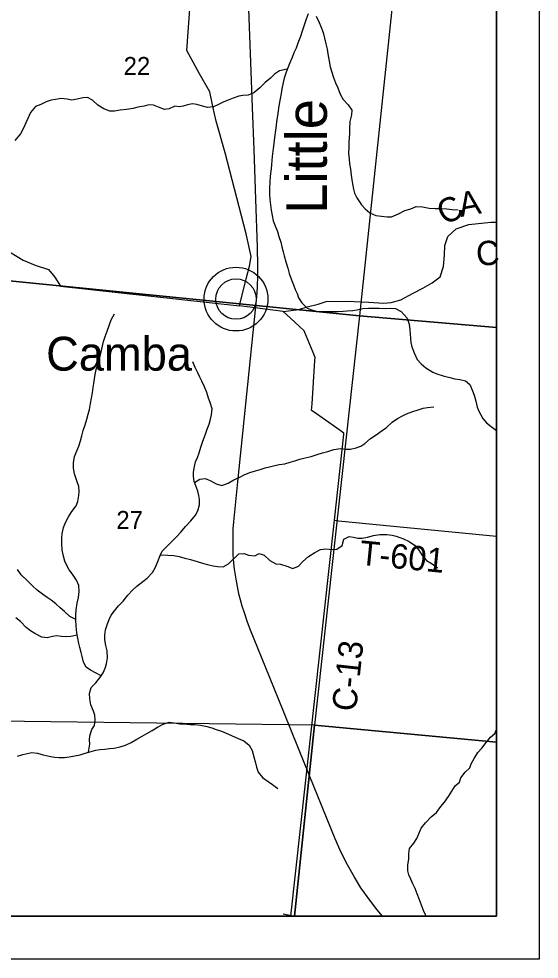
# Model space of a CAD drawing. Extents: x 0 to 34, y 0 to 22.
# Drawn here: x 29.202 to 30.417, y 14 to 16.193 of the extents above; entities that cross this region are included whole.
import ezdxf

# ---------------------------------------------------------------- set-up
doc = ezdxf.new("R2010")
doc.units = 0
for name, color, linetype in [('GM_X_Corporation', 7, 'Continuous'), ('GM_X_County_Road', 7, 'Continuous'), ('GM_X_County_Road_Text', 7, 'Continuous'), ('GM_X_Major_River', 7, 'Continuous'), ('GM_X_Major_River_Text', 7, 'Continuous'), ('GM_X_Minor_River', 7, 'Continuous'), ('GM_X_Rail_Line', 7, 'Continuous'), ('GM_X_Section_Text', 7, 'Continuous'), ('GM_X_Township_Road', 7, 'Continuous'), ('GM_X_Township_Road_Text', 7, 'Continuous'), ('GM_X_Unincorporated', 7, 'Continuous'), ('GM_X_Unincorporated_Location', 7, 'Continuous'), ('GM_X_Unincorporated_Text', 7, 'Continuous'), ('SH_Data', 7, 'Continuous')]:
    doc.layers.add(name, color=color, linetype=linetype)

msp = doc.modelspace()

# ---------------------------------------------------------------- linework, layer by layer
at = {"layer": 'GM_X_Corporation'}
msp.add_lwpolyline([(25.8273, 14.1), (30.3167, 14.1), (30.3167, 19.5906)], dxfattribs=at)
for points in [[(30.115, 16.6136), (29.9973, 15.5007), (29.0551, 15.5941), (29.176, 16.6858)], [(30.3167, 15.4729), (30.3167, 16.5908), (30.115, 16.6136), (29.9973, 15.5007)], [(29.9973, 15.5007), (29.8921, 14.5457), (28.9075, 14.5584), (29.0551, 15.5941)], [(30.3167, 14.5061), (30.3167, 15.4729), (29.9973, 15.5007), (29.8921, 14.5457)], [(28.8409, 14.1), (29.8452, 14.1), (29.8921, 14.5457), (28.9075, 14.5584)], [(29.8452, 14.1), (30.3167, 14.1), (30.3167, 14.5061), (29.8921, 14.5457)]]:
    msp.add_lwpolyline(points, close=True, dxfattribs=at)
at = {"layer": 'GM_X_County_Road'}
msp.add_line((29.8192, 15.5102), (29.7173, 15.5239), dxfattribs=at)
for points in [[(29.7173, 15.5239), (29.7329, 15.5869), (29.7403, 15.6165), (29.7444, 15.6389), (29.7328, 15.6915), (29.684, 15.8801), (29.6625, 15.9547), (29.6552, 15.9884), (29.6478, 16.0229), (29.6238, 16.0649), (29.5944, 16.119), (29.6075, 16.3028)], [(29.8192, 15.5102), (29.8554, 15.515), (29.8754, 15.5216), (29.9004, 15.5278), (29.9193, 15.5335), (29.9673, 15.5342), (30.0191, 15.5321), (30.0539, 15.53), (30.0713, 15.5316), (30.0936, 15.5378), (30.1227, 15.5535), (30.145, 15.5646), (30.1669, 15.5772), (30.1853, 15.5913), (30.1936, 15.6152), (30.1957, 15.6422), (30.196, 15.6646), (30.2035, 15.6854), (30.2231, 15.7034), (30.2522, 15.7137), (30.3036, 15.7189), (30.3167, 15.7188)], [(29.1663, 15.6581), (29.2121, 15.6303), (29.2398, 15.6186), (29.2716, 15.6086), (29.2861, 15.5904), (29.2994, 15.5696), (29.7173, 15.5239)], [(29.8366, 14.1), (29.9385, 15.0235), (29.9605, 15.2238), (29.9608, 15.2264), (29.9465, 15.2365), (29.8887, 15.2769), (29.8854, 15.2792), (29.8864, 15.2953), (29.8932, 15.3958), (29.8937, 15.4033), (29.8889, 15.415), (29.8699, 15.4616), (29.8683, 15.4656), (29.8566, 15.4763), (29.8267, 15.5034), (29.8192, 15.5102)]]:
    msp.add_lwpolyline(points, dxfattribs=at)
at = {"layer": 'GM_X_Major_River'}
for points in [[(29.8773, 16.2045), (29.8726, 16.1924), (29.868, 16.1784), (29.8637, 16.164), (29.8598, 16.1515), (29.8536, 16.136), (29.849, 16.1247), (29.8436, 16.1138), (29.8397, 16.1028), (29.8343, 16.0907), (29.8297, 16.0786), (29.8262, 16.0688), (29.8215, 16.0544), (29.8192, 16.0442), (29.816, 16.0295), (29.8144, 16.0189), (29.812, 16.0064), (29.8092, 15.9901), (29.8072, 15.9787), (29.8056, 15.967), (29.8036, 15.9538), (29.8024, 15.9439), (29.8012, 15.9333), (29.7991, 15.9166), (29.7971, 15.9026), (29.7955, 15.8905), (29.7935, 15.8716), (29.7918, 15.8534), (29.7909, 15.8435), (29.7889, 15.8261), (29.7876, 15.8117), (29.7871, 15.7977), (29.787, 15.7837), (29.788, 15.7715), (29.7894, 15.7594), (29.7908, 15.7465), (29.793, 15.734), (29.7959, 15.7222), (29.8, 15.71), (29.8055, 15.6974), (29.8092, 15.6857), (29.8132, 15.672), (29.8162, 15.6613), (29.8191, 15.6496), (29.8217, 15.6401), (29.8253, 15.6264), (29.8297, 15.6115), (29.833, 15.599), (29.8386, 15.5845), (29.8434, 15.5724), (29.8474, 15.5617), (29.8515, 15.5522), (29.8552, 15.5427), (29.8626, 15.5305), (29.875, 15.5183), (29.8848, 15.514), (29.8991, 15.5108), (29.9124, 15.5107), (29.9222, 15.5102)], [(29.9222, 15.5102), (29.9335, 15.5101), (29.9475, 15.5108), (29.9588, 15.5114), (29.9687, 15.5117), (29.9815, 15.5131), (29.9914, 15.5142), (30.0046, 15.5171), (30.0179, 15.5181), (30.0432, 15.5179), (30.0575, 15.5174), (30.0689, 15.518), (30.081, 15.5172), (30.0941, 15.5106), (30.1084, 15.4949), (30.1128, 15.4812), (30.1145, 15.468), (30.1156, 15.4581), (30.1163, 15.4478), (30.1173, 15.438), (30.1191, 15.4281), (30.1246, 15.4137), (30.1317, 15.3988), (30.1411, 15.3881), (30.1519, 15.3793), (30.1681, 15.3693), (30.1779, 15.3654), (30.1926, 15.3603), (30.208, 15.3564), (30.2201, 15.3537), (30.2311, 15.3517), (30.2443, 15.3485), (30.2551, 15.3401), (30.2611, 15.3256), (30.2651, 15.315), (30.2684, 15.3013), (30.2721, 15.2876), (30.2761, 15.2777), (30.2847, 15.261), (30.294, 15.2506), (30.3049, 15.2426), (30.3167, 15.2328)]]:
    msp.add_lwpolyline(points, dxfattribs=at)
at = {"layer": 'GM_X_Minor_River'}
for points in [[(29.8964, 16.1991), (29.9027, 16.1846), (29.9072, 16.1748), (29.9121, 16.1611), (29.9188, 16.1345), (29.9217, 16.122), (29.9236, 16.1114), (29.9265, 16.0939), (29.9291, 16.0814), (29.9317, 16.0712), (29.9369, 16.056), (29.9414, 16.0435), (29.9467, 16.0324), (29.9519, 16.0172), (29.9594, 16.0047), (29.9711, 15.9925), (29.9793, 15.9796), (29.9789, 15.9694), (29.9747, 15.9535), (29.9742, 15.9353), (29.9742, 15.9258), (29.9726, 15.9061), (29.9725, 15.894), (29.9717, 15.8788), (29.9728, 15.8659), (29.9742, 15.8549), (29.9761, 15.8424), (29.9779, 15.8283), (29.979, 15.8177), (29.9808, 15.8079), (29.9831, 15.7961), (29.9857, 15.7866), (29.9909, 15.7752), (30.0018, 15.7592), (30.0101, 15.7497), (30.0214, 15.7402), (30.035, 15.7345), (30.0486, 15.7329), (30.0614, 15.7313), (30.072, 15.7309), (30.0886, 15.738), (30.103, 15.7459), (30.1167, 15.75), (30.1295, 15.7553), (30.1439, 15.7548), (30.1601, 15.7517), (30.1741, 15.7505), (30.1892, 15.7508), (30.2009, 15.7496), (30.2138, 15.7484), (30.2278, 15.7472)], [(29.8286, 16.0755), (29.8104, 16.0717), (29.7986, 16.0638), (29.7892, 16.0548), (29.7774, 16.0446), (29.7649, 16.0317), (29.7508, 16.0204), (29.7372, 16.0152), (29.7251, 16.0141), (29.7153, 16.0123), (29.702, 16.0078), (29.6907, 16.0029), (29.6808, 15.9991), (29.6664, 15.9924), (29.6566, 15.9879), (29.6426, 15.9864), (29.6309, 15.9891), (29.6173, 15.993), (29.6075, 15.9946), (29.5958, 15.9927), (29.5859, 15.9893), (29.5761, 15.9879), (29.5659, 15.9891), (29.553, 15.9827), (29.5417, 15.9816), (29.5277, 15.9873), (29.5164, 15.9919), (29.5054, 15.9924), (29.4948, 15.9894), (29.4801, 15.9868), (29.4691, 15.9838), (29.4532, 15.9816), (29.4385, 15.9802), (29.4256, 15.9779), (29.4143, 15.9776), (29.4007, 15.983), (29.3867, 15.9918), (29.3743, 16.0036), (29.3623, 16.0097), (29.3517, 16.009), (29.3384, 16.0056), (29.3248, 16.0034), (29.3146, 16.0057), (29.301, 16.0069), (29.2874, 16.0051), (29.2772, 16.0033), (29.2658, 15.9991), (29.253, 15.9935), (29.2412, 15.9883), (29.2294, 15.9743), (29.2233, 15.9607), (29.2184, 15.9504), (29.2127, 15.9383), (29.2058, 15.9247), (29.1929, 15.9092)], [(29.3942, 14.6609), (29.3825, 14.6673), (29.3693, 14.6738), (29.3595, 14.6807), (29.3528, 14.6929), (29.3498, 14.7061), (29.3476, 14.7156), (29.3442, 14.7266), (29.3424, 14.7361), (29.3394, 14.749), (29.3372, 14.7608), (29.3358, 14.7767), (29.3347, 14.7923), (29.3351, 14.8029), (29.3359, 14.8146), (29.3383, 14.8305), (29.3413, 14.8434), (29.3429, 14.8574), (29.3422, 14.8711), (29.337, 14.884), (29.3276, 14.8977), (29.3193, 14.9083), (29.3137, 14.9178), (29.3096, 14.9284), (29.3055, 14.9429), (29.3033, 14.955), (29.3022, 14.9694), (29.3026, 14.9823), (29.3034, 14.9922), (29.3061, 15.0065), (29.3111, 15.0183), (29.3183, 15.0315), (29.326, 15.044), (29.3358, 15.0572), (29.3397, 15.067), (29.3424, 15.0811), (29.3428, 15.0905), (29.3417, 15.1023), (29.3372, 15.1159), (29.3316, 15.1315), (29.3294, 15.1452), (29.3298, 15.1573), (29.3318, 15.1721), (29.3417, 15.1967), (29.3456, 15.2092), (29.349, 15.2205), (29.3525, 15.233), (29.3567, 15.2463), (29.3605, 15.2595), (29.364, 15.2712), (29.3667, 15.2822), (29.3694, 15.2959), (29.3713, 15.308), (29.374, 15.3205), (29.3756, 15.3334), (29.3768, 15.3428), (29.3787, 15.3538), (29.3799, 15.3637), (29.3822, 15.3754), (29.3864, 15.389), (29.3899, 15.3989), (29.3937, 15.4125), (29.3968, 15.4265), (29.3999, 15.4401), (29.4033, 15.4519), (29.4083, 15.4647), (29.4129, 15.478), (29.4178, 15.4912), (29.4251, 15.5049)], [(29.3646, 14.4827), (29.3674, 14.5014), (29.3671, 14.5113), (29.3679, 14.5211), (29.3725, 14.5355), (29.3786, 14.5453), (29.3805, 14.5582), (29.3794, 14.5688), (29.3761, 14.5787), (29.3701, 14.5931), (29.3679, 14.6075), (29.3672, 14.6197), (29.371, 14.6333), (29.3817, 14.6446), (29.3923, 14.6582), (29.3992, 14.668), (29.4034, 14.6786), (29.4064, 14.6888), (29.4091, 14.7025), (29.4081, 14.7188), (29.4051, 14.7317), (29.4025, 14.7446), (29.4026, 14.7556), (29.4041, 14.7684), (29.4091, 14.7821), (29.4129, 14.7919), (29.4175, 14.8021), (29.4255, 14.8127), (29.4346, 14.8244), (29.4452, 14.835), (29.4566, 14.8493), (29.468, 14.8614), (29.4775, 14.8697), (29.4915, 14.881), (29.5014, 14.8889), (29.5143, 14.9017), (29.5212, 14.9146), (29.5261, 14.9271), (29.5319, 14.9411), (29.5368, 14.9513), (29.549, 14.9641), (29.5607, 14.9754), (29.5706, 14.9856), (29.5801, 14.9962), (29.5911, 15.0094), (29.6037, 15.0226), (29.6147, 15.0355), (29.62, 15.0453), (29.6235, 15.0597), (29.6235, 15.0722), (29.6224, 15.0817), (29.6202, 15.0912), (29.615, 15.1041), (29.6112, 15.1143), (29.6101, 15.1257), (29.6098, 15.1352), (29.611, 15.145), (29.6145, 15.1598), (29.6187, 15.17), (29.6232, 15.1806), (29.6271, 15.1939), (29.6317, 15.2082), (29.6378, 15.2241), (29.642, 15.2362), (29.6466, 15.2476), (29.6497, 15.2597), (29.652, 15.2696), (29.6532, 15.2836), (29.6487, 15.298), (29.645, 15.3086), (29.6409, 15.3215), (29.6356, 15.3345), (29.6293, 15.3481), (29.6248, 15.3576), (29.6195, 15.3675), (29.6135, 15.3797), (29.6079, 15.393)], [(29.6123, 15.1113), (29.6245, 15.1192), (29.637, 15.1207), (29.6487, 15.1161), (29.663, 15.1084), (29.6762, 15.1046), (29.691, 15.1098), (29.7038, 15.1177), (29.7167, 15.1237), (29.7277, 15.1293), (29.741, 15.135), (29.7542, 15.1387), (29.7652, 15.1421), (29.7773, 15.1458), (29.7871, 15.1484), (29.7992, 15.1514), (29.8098, 15.154), (29.8227, 15.1554), (29.8355, 15.1588), (29.8461, 15.1622), (29.8583, 15.1663), (29.8704, 15.1693), (29.8847, 15.1722), (29.8987, 15.1767), (29.9109, 15.1808), (29.923, 15.1842), (29.937, 15.1883), (29.9525, 15.1909), (29.9661, 15.1897), (29.9759, 15.1896), (29.9891, 15.1922), (30.0001, 15.1967), (30.01, 15.2027), (30.0232, 15.2144), (30.0361, 15.2227), (30.0502, 15.2329), (30.0604, 15.2397), (30.0733, 15.2521), (30.0862, 15.2612), (30.0972, 15.2675), (30.107, 15.2717), (30.1218, 15.2773), (30.1339, 15.2814), (30.146, 15.2851), (30.1562, 15.2862), (30.1706, 15.2881)], [(29.5329, 14.9432), (29.55, 14.9421), (29.5636, 14.9417), (29.5765, 14.939), (29.5893, 14.9355), (29.6029, 14.932), (29.6184, 14.9274), (29.6308, 14.9232), (29.6425, 14.9201), (29.6557, 14.9174), (29.6659, 14.9158), (29.6788, 14.915), (29.6917, 14.9218), (29.7152, 14.9452), (29.7277, 14.9459), (29.7382, 14.9424), (29.7526, 14.9408), (29.7632, 14.9461), (29.7749, 14.9419), (29.7881, 14.9301), (29.8016, 14.9221), (29.813, 14.9212), (29.8273, 14.9162), (29.8413, 14.9113), (29.8549, 14.9165), (29.8648, 14.9275), (29.8781, 14.9391), (29.8928, 14.9486), (29.9061, 14.9553), (29.9186, 14.9568), (29.9344, 14.9552), (29.9446, 14.9563), (29.9564, 14.9649), (29.9606, 14.9797), (29.9727, 14.9857), (29.9833, 14.9842), (29.9931, 14.9818), (30.0033, 14.9818), (30.0158, 14.984), (30.0302, 14.9881), (30.045, 14.9903), (30.0608, 14.9902), (30.0733, 14.9891), (30.0831, 14.9867), (30.0997, 14.9806), (30.1129, 14.9737), (30.1253, 14.9657), (30.1359, 14.9535), (30.1438, 14.9417), (30.1539, 14.9299), (30.1667, 14.9219), (30.1795, 14.9128)], [(29.3347, 14.7923), (29.3207, 14.7991), (29.3083, 14.8109), (29.2985, 14.8197), (29.2887, 14.8288), (29.2778, 14.8376), (29.268, 14.8437), (29.2575, 14.8514), (29.2447, 14.8609), (29.2349, 14.87), (29.2217, 14.8834), (29.2078, 14.8967), (29.1991, 14.9089)], [(29.3381, 14.7557), (29.3236, 14.7525), (29.3137, 14.7518), (29.302, 14.7526), (29.2911, 14.7542), (29.2808, 14.7523), (29.268, 14.7497), (29.2555, 14.7513), (29.2397, 14.7597), (29.2295, 14.7658), (29.2193, 14.7738), (29.2058, 14.7872), (29.1952, 14.7963)], [(29.1991, 14.4737), (29.2112, 14.4775), (29.2324, 14.4819), (29.2456, 14.4803), (29.2592, 14.4769), (29.2728, 14.4738), (29.2853, 14.4714), (29.2951, 14.4703), (29.3087, 14.4706), (29.3193, 14.4721), (29.3329, 14.4739), (29.345, 14.4765), (29.3549, 14.4799), (29.3677, 14.4836), (29.3821, 14.4873), (29.392, 14.4892), (29.4025, 14.4899), (29.4135, 14.491), (29.4237, 14.492), (29.4388, 14.495), (29.4513, 14.4991), (29.4646, 14.5051), (29.4771, 14.513), (29.4896, 14.5202), (29.5006, 14.5266), (29.5135, 14.5333), (29.526, 14.5412), (29.5392, 14.5484), (29.5529, 14.5525), (29.5646, 14.5513), (29.5778, 14.5486), (29.5876, 14.5485), (29.602, 14.5477), (29.6125, 14.5473), (29.6258, 14.5457), (29.6375, 14.5438), (29.6522, 14.5399), (29.6628, 14.5357), (29.6748, 14.5318), (29.6858, 14.5273), (29.6982, 14.5219), (29.7141, 14.515), (29.7269, 14.5089), (29.7393, 14.4993), (29.7468, 14.4868), (29.7502, 14.472), (29.7543, 14.4576), (29.7569, 14.4481), (29.7606, 14.4363), (29.7704, 14.4234), (29.7843, 14.4146), (29.7941, 14.4074), (29.8069, 14.3982)], [(30.1528, 14.1), (30.1511, 14.1037), (30.1462, 14.1136), (30.1421, 14.1261), (30.1372, 14.1383), (30.132, 14.1523), (30.1268, 14.1648), (30.1219, 14.1759), (30.1167, 14.1865), (30.1122, 14.1964), (30.1103, 14.2062), (30.1104, 14.2195), (30.112, 14.2339), (30.1124, 14.246), (30.1136, 14.2585), (30.1238, 14.2702), (30.1307, 14.2812), (30.1356, 14.2925), (30.1414, 14.3054), (30.1513, 14.3182), (30.1642, 14.3322), (30.1767, 14.342), (30.1869, 14.356), (30.1957, 14.3662), (30.2048, 14.3794), (30.2124, 14.3922), (30.2208, 14.4043), (30.2307, 14.413), (30.2341, 14.4232), (30.2436, 14.4364), (30.255, 14.4459), (30.2581, 14.4557), (30.2645, 14.4682), (30.2733, 14.4818), (30.2824, 14.4924), (30.293, 14.5052), (30.3033, 14.518), (30.3128, 14.5263), (30.3167, 14.5357)], [(29.8426, 14.1), (29.8344, 14.1021), (29.8192, 14.1052)]]:
    msp.add_lwpolyline(points, dxfattribs=at)
at = {"layer": 'GM_X_Rail_Line'}
msp.add_lwpolyline([(30.051, 14.1), (30.0383, 14.115), (30.0237, 14.1344), (30.0007, 14.1667), (29.9854, 14.1912), (29.9692, 14.2198), (29.9542, 14.2488), (29.9403, 14.2803), (29.871, 14.4508), (29.8203, 14.5761), (29.7869, 14.6587), (29.7428, 14.7671), (29.735, 14.7884), (29.7284, 14.8078), (29.7234, 14.8234), (29.7195, 14.8381), (29.7166, 14.849), (29.7141, 14.8607), (29.7091, 14.8862), (29.7057, 14.9097), (29.704, 14.924), (29.7027, 14.9429), (29.702, 14.9579), (29.702, 14.9744), (29.7021, 14.9902), (29.7027, 15.0038), (29.7037, 15.0197), (29.7134, 15.1131), (29.7576, 15.5443), (29.7592, 15.5672), (29.7598, 15.5953), (29.7602, 15.6159), (29.7593, 15.6604), (29.7554, 15.7725), (29.751, 15.8883), (29.7476, 15.9863), (29.7374, 16.2588)], dxfattribs=at)
at = {"layer": 'GM_X_Township_Road'}
msp.add_lwpolyline([(29.9385, 15.0235), (29.9484, 15.0224), (30.3167, 14.9869)], dxfattribs=at)
at = {"layer": 'GM_X_Unincorporated'}
for radius in [0.0744, 0.0472]:
    msp.add_circle((29.7089, 15.5394), radius, dxfattribs=at)
at = {"layer": 'GM_X_Unincorporated_Location'}
msp.add_line((29.7089, 15.5394), (29.7089, 15.5394), dxfattribs=at)
at = {"layer": 'SH_Data'}
for points in [[(23.4167, 21), (30.4167, 21), (30.4167, 14), (23.4167, 14)], [(23.5167, 20.9), (30.3167, 20.9), (30.3167, 14.1), (23.5167, 14.1)]]:
    msp.add_lwpolyline(points, close=True, dxfattribs=at)

# ---------------------------------------------------------------- texts
at = {"layer": 'GM_X_County_Road_Text'}
for s, height, rotation, p in [('A', 0.0568, 9.9546, (30.2337, 15.7308)), ('C', 0.0568, 28.7108, (30.1974, 15.71)), ('C', 0.0568, 3.5853, (30.2709, 15.6168)), ('C-13', 0.05682, 83.8109, (29.989, 14.5761))]:
    msp.add_text(s, height=height, rotation=rotation, dxfattribs=at).set_placement(p)
at = {"layer": 'GM_X_Major_River_Text'}
msp.add_text('Little', height=0.09471, rotation=89.9999, dxfattribs=at).set_placement((29.9211, 15.7384))
at = {"layer": 'GM_X_Section_Text'}
for s, p in [('22', (29.4466, 16.0621)), ('27', (29.4296, 15.0034))]:
    msp.add_text(s, height=0.04186, rotation=0, dxfattribs=at).set_placement(p)
at = {"layer": 'GM_X_Township_Road_Text'}
msp.add_text('T-601', height=0.05682, rotation=354.3731, dxfattribs=at).set_placement((29.9953, 14.9202))
at = {"layer": 'GM_X_Unincorporated_Text'}
msp.add_text('Camba', height=0.07898, rotation=0, dxfattribs=at).set_placement((29.2658, 15.3725))

doc.saveas('drawing.dxf')
